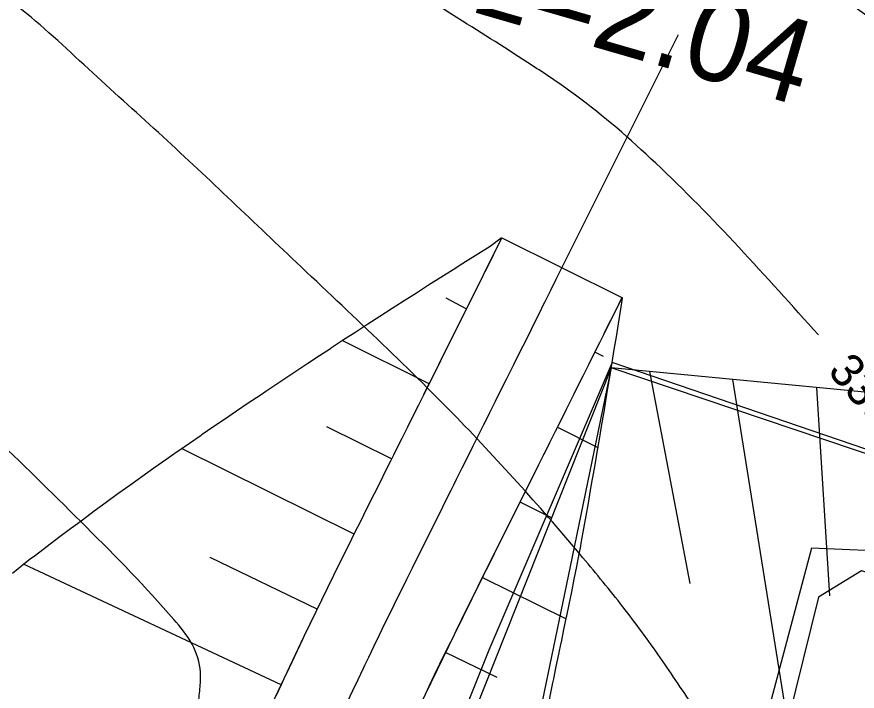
# Model space of a CAD drawing. Extents: x -564037 to -563827, y -1163561 to -1163412.
# Drawn here: x -563899.01 to -563886.48, y -1163485.99 to -1163475.94 of the extents above; entities that cross this region are included whole.
import ezdxf

# ---------------------------------------------------------------- set-up
doc = ezdxf.new("R2010")
doc.units = 0
for name, color, linetype in [('_popis staničení RT1', 7, 'Continuous'), ('Default', 7, 'Continuous'), ('Line', 7, 'Continuous'), ('Vrstva 24', 7, 'Continuous'), ('Vrstva 25', 7, 'Continuous'), ('Vrstva 26', 7, 'Continuous')]:
    doc.layers.add(name, color=color, linetype=linetype)

msp = doc.modelspace()

# ---------------------------------------------------------------- linework, layer by layer
msp.add_line((-563890.151, -1163481.173), (-563898.85, -1163503.099))
for points in [[(-563894.079, -1163486.154), (-563894, -1163485.986), (-563893.921, -1163485.819), (-563893.841, -1163485.652), (-563893.819, -1163485.606), (-563893.761, -1163485.485), (-563893.681, -1163485.319), (-563893.601, -1163485.152), (-563893.52, -1163484.986), (-563893.439, -1163484.819), (-563893.383, -1163484.706), (-563893.357, -1163484.653), (-563893.275, -1163484.487), (-563893.193, -1163484.322), (-563893.116, -1163484.167), (-563893.111, -1163484.156), (-563893.028, -1163483.99), (-563892.946, -1163483.825), (-563892.939, -1163483.81), (-563892.863, -1163483.659), (-563892.781, -1163483.494), (-563892.698, -1163483.328), (-563892.616, -1163483.162), (-563892.533, -1163482.997), (-563892.493, -1163482.915), (-563892.451, -1163482.831), (-563892.368, -1163482.666), (-563892.286, -1163482.5), (-563892.203, -1163482.335), (-563892.121, -1163482.169), (-563892.047, -1163482.02), (-563892.038, -1163482.003), (-563891.956, -1163481.838), (-563891.873, -1163481.672), (-563891.791, -1163481.507), (-563891.708, -1163481.341), (-563891.626, -1163481.175), (-563891.601, -1163481.125), (-563891.543, -1163481.01), (-563891.461, -1163480.844), (-563891.378, -1163480.679), (-563891.296, -1163480.513), (-563891.213, -1163480.347), (-563891.155, -1163480.23), (-563891.131, -1163480.182), (-563891.048, -1163480.016), (-563890.966, -1163479.851), (-563889.152, -1163476.21), (-563889.15, -1163476.207)], [(-563899.068, -1163484.235), (-563898.901, -1163484.098), (-563898.805, -1163484.023), (-563898.727, -1163483.964), (-563898.553, -1163483.832), (-563898.379, -1163483.7), (-563898.203, -1163483.568), (-563898.155, -1163483.532), (-563898.028, -1163483.437), (-563897.851, -1163483.307), (-563897.675, -1163483.178), (-563897.498, -1163483.049), (-563897.32, -1163482.921), (-563897.199, -1163482.834), (-563897.142, -1163482.793), (-563896.963, -1163482.666), (-563896.785, -1163482.54), (-563896.617, -1163482.422), (-563896.606, -1163482.415), (-563896.432, -1163482.295), (-563896.257, -1163482.175), (-563896.242, -1163482.164), (-563896.083, -1163482.055), (-563895.908, -1163481.936), (-563895.732, -1163481.816), (-563895.556, -1163481.697), (-563895.38, -1163481.578), (-563895.293, -1163481.52), (-563895.203, -1163481.46), (-563895.026, -1163481.341), (-563894.849, -1163481.223), (-563894.671, -1163481.105), (-563894.493, -1163480.987), (-563894.332, -1163480.882), (-563894.314, -1163480.87), (-563894.135, -1163480.752), (-563893.955, -1163480.635), (-563893.775, -1163480.518), (-563893.595, -1163480.401), (-563893.414, -1163480.285), (-563893.359, -1163480.249), (-563893.232, -1163480.168), (-563893.051, -1163480.052), (-563892.869, -1163479.936), (-563892.686, -1163479.82), (-563892.503, -1163479.705), (-563892.374, -1163479.623), (-563892.32, -1163479.589), (-563892.136, -1163479.474), (-563891.952, -1163479.359), (-563891.79, -1163479.234)], [(-563898.27, -1163493.54), (-563897.913, -1163492.595), (-563897.753, -1163492.179), (-563897.547, -1163491.654), (-563897.269, -1163490.958), (-563897.171, -1163490.716), (-563896.89, -1163490.033), (-563896.786, -1163489.783), (-563896.391, -1163488.853), (-563895.988, -1163487.927), (-563895.979, -1163487.907), (-563895.575, -1163487.005), (-563895.153, -1163486.088), (-563895.019, -1163485.803), (-563894.721, -1163485.175), (-563894.281, -1163484.266), (-563894.011, -1163483.721), (-563893.834, -1163483.364), (-563893.388, -1163482.469), (-563892.942, -1163481.574), (-563892.496, -1163480.679), (-563892.461, -1163480.609), (-563892.05, -1163479.784), (-563891.777, -1163479.236)], [(-563895.142, -1163486.066), (-563895.063, -1163485.897), (-563895.019, -1163485.803), (-563894.984, -1163485.728), (-563894.904, -1163485.559), (-563894.824, -1163485.39), (-563894.743, -1163485.221), (-563894.721, -1163485.175), (-563894.663, -1163485.053), (-563894.582, -1163484.884), (-563894.5, -1163484.716), (-563894.419, -1163484.548), (-563894.337, -1163484.38), (-563894.281, -1163484.266), (-563894.255, -1163484.212), (-563894.172, -1163484.045), (-563894.089, -1163483.877), (-563894.011, -1163483.721), (-563894.006, -1163483.71), (-563893.923, -1163483.544), (-563893.841, -1163483.379), (-563893.834, -1163483.364), (-563893.758, -1163483.213), (-563893.676, -1163483.048), (-563893.593, -1163482.882), (-563893.511, -1163482.716), (-563893.428, -1163482.551), (-563893.388, -1163482.469), (-563893.346, -1163482.385), (-563893.263, -1163482.22), (-563893.181, -1163482.054), (-563893.098, -1163481.889), (-563893.016, -1163481.723), (-563892.942, -1163481.574), (-563892.933, -1163481.557), (-563892.851, -1163481.392), (-563892.768, -1163481.226), (-563892.686, -1163481.061), (-563892.603, -1163480.895), (-563892.521, -1163480.729), (-563892.496, -1163480.679), (-563892.438, -1163480.564), (-563892.356, -1163480.398), (-563892.273, -1163480.233), (-563892.191, -1163480.067), (-563892.108, -1163479.902), (-563892.05, -1163479.784), (-563892.026, -1163479.736), (-563891.943, -1163479.57), (-563891.861, -1163479.405), (-563891.778, -1163479.239), (-563891.777, -1163479.236), (-563889.979, -1163480.131)], [(-563891.79, -1163479.234), (-563891.79, -1163479.229)], [(-563896.046, -1163493.311), (-563895.888, -1163492.903), (-563895.687, -1163492.389), (-563895.414, -1163491.706), (-563895.318, -1163491.47), (-563895.043, -1163490.8), (-563894.941, -1163490.555), (-563894.554, -1163489.643), (-563894.158, -1163488.736), (-563894.15, -1163488.716), (-563893.754, -1163487.832), (-563893.34, -1163486.933), (-563893.209, -1163486.653), (-563892.917, -1163486.038), (-563892.485, -1163485.147), (-563892.221, -1163484.613), (-563892.044, -1163484.256), (-563891.598, -1163483.361), (-563891.152, -1163482.466), (-563890.706, -1163481.571), (-563890.671, -1163481.5), (-563890.26, -1163480.676), (-563889.986, -1163480.127)], [(-563892.917, -1163486.038), (-563892.86, -1163485.918), (-563892.78, -1163485.753), (-563892.701, -1163485.588), (-563892.621, -1163485.423), (-563892.54, -1163485.259), (-563892.485, -1163485.147), (-563892.46, -1163485.094), (-563892.379, -1163484.93), (-563892.297, -1163484.766), (-563892.221, -1163484.613), (-563892.216, -1163484.602), (-563892.133, -1163484.436), (-563892.051, -1163484.271), (-563892.044, -1163484.256), (-563891.968, -1163484.105), (-563891.886, -1163483.94), (-563891.803, -1163483.774), (-563891.721, -1163483.608), (-563891.638, -1163483.443), (-563891.598, -1163483.361), (-563891.556, -1163483.277), (-563891.473, -1163483.112), (-563891.391, -1163482.946), (-563891.308, -1163482.78), (-563891.226, -1163482.615), (-563891.152, -1163482.466), (-563891.143, -1163482.449), (-563891.061, -1163482.284), (-563890.978, -1163482.118), (-563890.896, -1163481.953), (-563890.813, -1163481.787), (-563890.731, -1163481.621), (-563890.706, -1163481.571), (-563890.648, -1163481.456), (-563890.566, -1163481.29), (-563890.483, -1163481.125), (-563890.401, -1163480.959), (-563890.318, -1163480.793), (-563890.26, -1163480.676), (-563890.236, -1163480.628), (-563890.153, -1163480.462), (-563890.071, -1163480.297), (-563889.988, -1163480.131), (-563889.986, -1163480.127)], [(-563891.079, -1163486.174), (-563891.042, -1163485.992), (-563891.016, -1163485.868), (-563891.004, -1163485.81), (-563890.967, -1163485.627), (-563890.929, -1163485.445), (-563890.893, -1163485.274), (-563890.891, -1163485.262), (-563890.852, -1163485.075), (-563890.813, -1163484.888), (-563890.81, -1163484.871), (-563890.774, -1163484.7), (-563890.736, -1163484.513), (-563890.698, -1163484.325), (-563890.66, -1163484.137), (-563890.624, -1163483.948), (-563890.607, -1163483.855), (-563890.59, -1163483.759), (-563890.556, -1163483.569), (-563890.522, -1163483.379), (-563890.488, -1163483.189), (-563890.455, -1163482.999), (-563890.425, -1163482.828), (-563890.422, -1163482.809), (-563890.389, -1163482.619), (-563890.356, -1163482.428), (-563890.324, -1163482.238), (-563890.291, -1163482.047), (-563890.259, -1163481.856), (-563890.25, -1163481.799), (-563890.227, -1163481.666), (-563890.196, -1163481.475), (-563890.164, -1163481.284), (-563890.133, -1163481.092), (-563890.102, -1163480.901), (-563890.08, -1163480.766), (-563890.071, -1163480.71), (-563890.041, -1163480.518), (-563890.01, -1163480.327), (-563889.98, -1163480.135), (-563889.979, -1163480.131)], [(-563878.137, -1163496.97), (-563876.837, -1163490), (-563879.296, -1163487.066), (-563881.987, -1163484.651), (-563882.119, -1163484.582), (-563882.455, -1163484.408), (-563883.788, -1163483.304), (-563883.864, -1163483.279), (-563884.159, -1163483.181), (-563884.226, -1163483.159), (-563884.302, -1163483.134), (-563884.34, -1163483.121), (-563884.386, -1163483.106), (-563884.482, -1163483.074), (-563884.592, -1163483.038), (-563884.718, -1163482.996), (-563884.865, -1163482.947), (-563884.978, -1163482.91), (-563885.376, -1163482.786), (-563885.4, -1163482.777), (-563885.486, -1163482.747), (-563885.596, -1163482.707), (-563890.151, -1163481.173)], [(-563882.19, -1163496.364), (-563880.778, -1163492.835), (-563880.808, -1163489.502), (-563880.527, -1163488.546), (-563880.34, -1163487.91), (-563881.995, -1163486.424), (-563882.215, -1163486.31), (-563882.772, -1163486.021), (-563884.984, -1163484.19), (-563885.111, -1163484.148), (-563885.233, -1163484.108), (-563885.348, -1163484.069), (-563885.478, -1163484.026), (-563885.544, -1163484.004), (-563885.623, -1163483.978), (-563885.788, -1163483.923), (-563887.164, -1163483.863), (-563888.153, -1163487.579), (-563890.867, -1163493.518)]]:
    msp.add_lwpolyline(points)
for points in [[(-563900.324, -1163505.882), (-563892.678, -1163503.006), (-563888.735, -1163501.906), (-563886.271, -1163502.018), (-563883.536, -1163500.684), (-563878.095, -1163497.234), (-563876.621, -1163489.849), (-563880.163, -1163485.998), (-563881.977, -1163484.515), (-563883.765, -1163483.269), (-563890.133, -1163481.092), (-563891.974, -1163485.382), (-563895.143, -1163493.304), (-563898.704, -1163502.458), (-563900.439, -1163505.855)], [(-563887.058, -1163484.593), (-563887.855, -1163487.81), (-563890.21, -1163493.633), (-563891.581, -1163498.253), (-563891.461, -1163499.576), (-563890.275, -1163499.82), (-563886.599, -1163499.649), (-563882.84, -1163497.558), (-563881.049, -1163492.941), (-563880.784, -1163487.979), (-563884.81, -1163484.679), (-563886.418, -1163484.198)]]:
    msp.add_lwpolyline(points, close=True)
at = {"layer": 'Default'}
msp.add_lwpolyline([(-563884.497, -1163481.718), (-563886.832, -1163481.493), (-563890.151, -1163481.173), (-563890.761, -1163484.133), (-563891.23, -1163486.411), (-563891.248, -1163486.496), (-563891.655, -1163487.489), (-563891.658, -1163487.497), (-563891.845, -1163487.951), (-563892.101, -1163488.575), (-563892.249, -1163488.936), (-563893.249, -1163491.302), (-563893.527, -1163491.96), (-563894.011, -1163493.107), (-563894.298, -1163493.726)], dxfattribs=at)
at = {"layer": 'Line'}
for p, q in [((-563892.611, -1163480.131), (-563892.304, -1163480.294)), ((-563889.986, -1163480.127), (-563889.979, -1163480.131)), ((-563892.862, -1163481.413), (-563894.158, -1163480.767)), ((-563890.261, -1163481.006), (-563890.392, -1163480.94)), ((-563889.579, -1163481.228), (-563888.976, -1163484.391)), ((-563887.07, -1163489.251), (-563888.335, -1163481.348)), ((-563887.091, -1163481.468), (-563886.894, -1163484.572)), ((-563894.39, -1163482.049), (-563893.419, -1163482.532)), ((-563890.949, -1163482.059), (-563890.345, -1163482.36)), ((-563893.976, -1163483.651), (-563896.552, -1163482.378)), ((-563891.038, -1163483.412), (-563891.506, -1163483.178)), ((-563896.131, -1163483.997), (-563894.527, -1163484.773)), ((-563895.065, -1163485.902), (-563898.905, -1163484.101)), ((-563892.064, -1163484.297), (-563890.819, -1163484.914)), ((-563891.847, -1163485.792), (-563892.617, -1163485.418))]:
    msp.add_line(p, q, dxfattribs=at)
at = {"layer": 'Vrstva 24'}
for points in [[(-563903.419, -1163497.029), (-563902.125, -1163495.59), (-563900.744, -1163494.039), (-563899.345, -1163492.505), (-563898.448, -1163491.553), (-563897.897, -1163490.941), (-563897.635, -1163490.622), (-563897.383, -1163490.29), (-563897.001, -1163489.401), (-563896.398, -1163486.71), (-563896.305, -1163486.212), (-563896.276, -1163485.962), (-563896.268, -1163485.713), (-563896.394, -1163485.294), (-563896.666, -1163484.924), (-563897.969, -1163483.548), (-563899.309, -1163482.237), (-563900.743, -1163480.898), (-563903.659, -1163478.289), (-563907.403, -1163474.951), (-563909.511, -1163473.024), (-563914.099, -1163468.742), (-563916.271, -1163466.637)], [(-563866.364, -1163497.311), (-563866.075, -1163496.511), (-563865.895, -1163495.533), (-563865.845, -1163494.553), (-563865.947, -1163493.507), (-563866.272, -1163492.388), (-563866.563, -1163491.699), (-563866.868, -1163491.02), (-563867.192, -1163490.352), (-563867.536, -1163489.691), (-563869.125, -1163486.92), (-563869.85, -1163485.772), (-563870.624, -1163484.653), (-563871.666, -1163483.346), (-563872.824, -1163482.142), (-563874.562, -1163480.618), (-563875.472, -1163479.893), (-563878.363, -1163477.556), (-563882.755, -1163474.046), (-563884.234, -1163472.969), (-563885.61, -1163472.026), (-563886.998, -1163471.1), (-563889.83, -1163469.34), (-563892.347, -1163467.891)]]:
    msp.add_spline(points, degree=3, dxfattribs=at)
at = {"layer": 'Vrstva 25'}
for points in [[(-563887.061, -1163480.683), (-563889.484, -1163478.121), (-563890.679, -1163477.108), (-563891.259, -1163476.707), (-563892.363, -1163476.003), (-563898.337, -1163472.154), (-563901.291, -1163470.247), (-563905.742, -1163467.169), (-563908.131, -1163465.28), (-563910.842, -1163462.928), (-563912.224, -1163461.617), (-563914.968, -1163458.534), (-563915.642, -1163457.658), (-563916.293, -1163456.766), (-563917.513, -1163454.928), (-563918.174, -1163453.842)], [(-563905.141, -1163510.37), (-563904.922, -1163510.229), (-563901.706, -1163508.177), (-563898.297, -1163505.868), (-563895.6, -1163504.013), (-563893.249, -1163502.324), (-563892.081, -1163501.469), (-563890.919, -1163500.608), (-563889.757, -1163499.746), (-563888.589, -1163498.892), (-563887.491, -1163498.145), (-563886.364, -1163497.441), (-563885.229, -1163496.747), (-563884.107, -1163496.03), (-563883.48, -1163495.59), (-563883.181, -1163495.349), (-563882.893, -1163495.092), (-563882.209, -1163494.336), (-563881.626, -1163493.502), (-563881.193, -1163492.783), (-563880.36, -1163491.213), (-563880.004, -1163490.417), (-563879.711, -1163489.616), (-563879.829, -1163489.186), (-563884.789, -1163483.345)]]:
    msp.add_spline(points, degree=3, dxfattribs=at)
at = {"layer": 'Vrstva 26'}
for points in [[(-563873.45, -1163489.454), (-563873.727, -1163488.976), (-563874.776, -1163487.436), (-563876.784, -1163484.893), (-563881.14, -1163480.242), (-563883.664, -1163478.013), (-563887.513, -1163475.075), (-563890.545, -1163473.024), (-563896.225, -1163469.436), (-563897.371, -1163468.706), (-563897.941, -1163468.337), (-563899.477, -1163467.352), (-563904.895, -1163463.746), (-563905.311, -1163463.453)], [(-563904.255, -1163504.408), (-563901.932, -1163502.584), (-563900.774, -1163501.667), (-563899.621, -1163500.744), (-563898.128, -1163499.495), (-563896.658, -1163498.219), (-563892.051, -1163494.217), (-563891.058, -1163493.351), (-563890.3, -1163492.602), (-563889.946, -1163492.201), (-563889.6, -1163491.789), (-563889.274, -1163491.333), (-563889.128, -1163491.092), (-563888.986, -1163490.845), (-563888.757, -1163490.393), (-563888.565, -1163489.929), (-563888.402, -1163489.454), (-563888.258, -1163488.97), (-563888.179, -1163488.634), (-563888.132, -1163488.29), (-563888.126, -1163487.946), (-563888.168, -1163487.609), (-563888.372, -1163487.087), (-563888.888, -1163486.275), (-563889.418, -1163485.493), (-563889.974, -1163484.737), (-563890.569, -1163484.004), (-563892.45, -1163481.915), (-563894.839, -1163479.601), (-563896.896, -1163477.665), (-563897.939, -1163476.713), (-563899, -1163475.779), (-563899.292, -1163475.563), (-563900.233, -1163474.949)]]:
    msp.add_spline(points, degree=3, dxfattribs=at)

# ---------------------------------------------------------------- texts
at = {"layer": '_popis staničení RT1'}
msp.add_text('   z=2.04', height=1.25, rotation=343.8679, dxfattribs=at).set_placement((-563893.569, -1163475.472))
at = {"layer": 'Vrstva 25'}
msp.add_text('330.00', height=0.5, rotation=310.6836, dxfattribs=at).set_placement((-563886.936, -1163481.23))

doc.saveas('drawing.dxf')
